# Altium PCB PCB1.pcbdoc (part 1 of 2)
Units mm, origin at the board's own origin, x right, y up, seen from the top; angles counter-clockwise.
Board outline 181.85 x 97.7 mm, 4 copper layers (Top Layer, GND, VCC, Bottom Layer); 121 components, 105 nets, 379 pads, 511 vias.
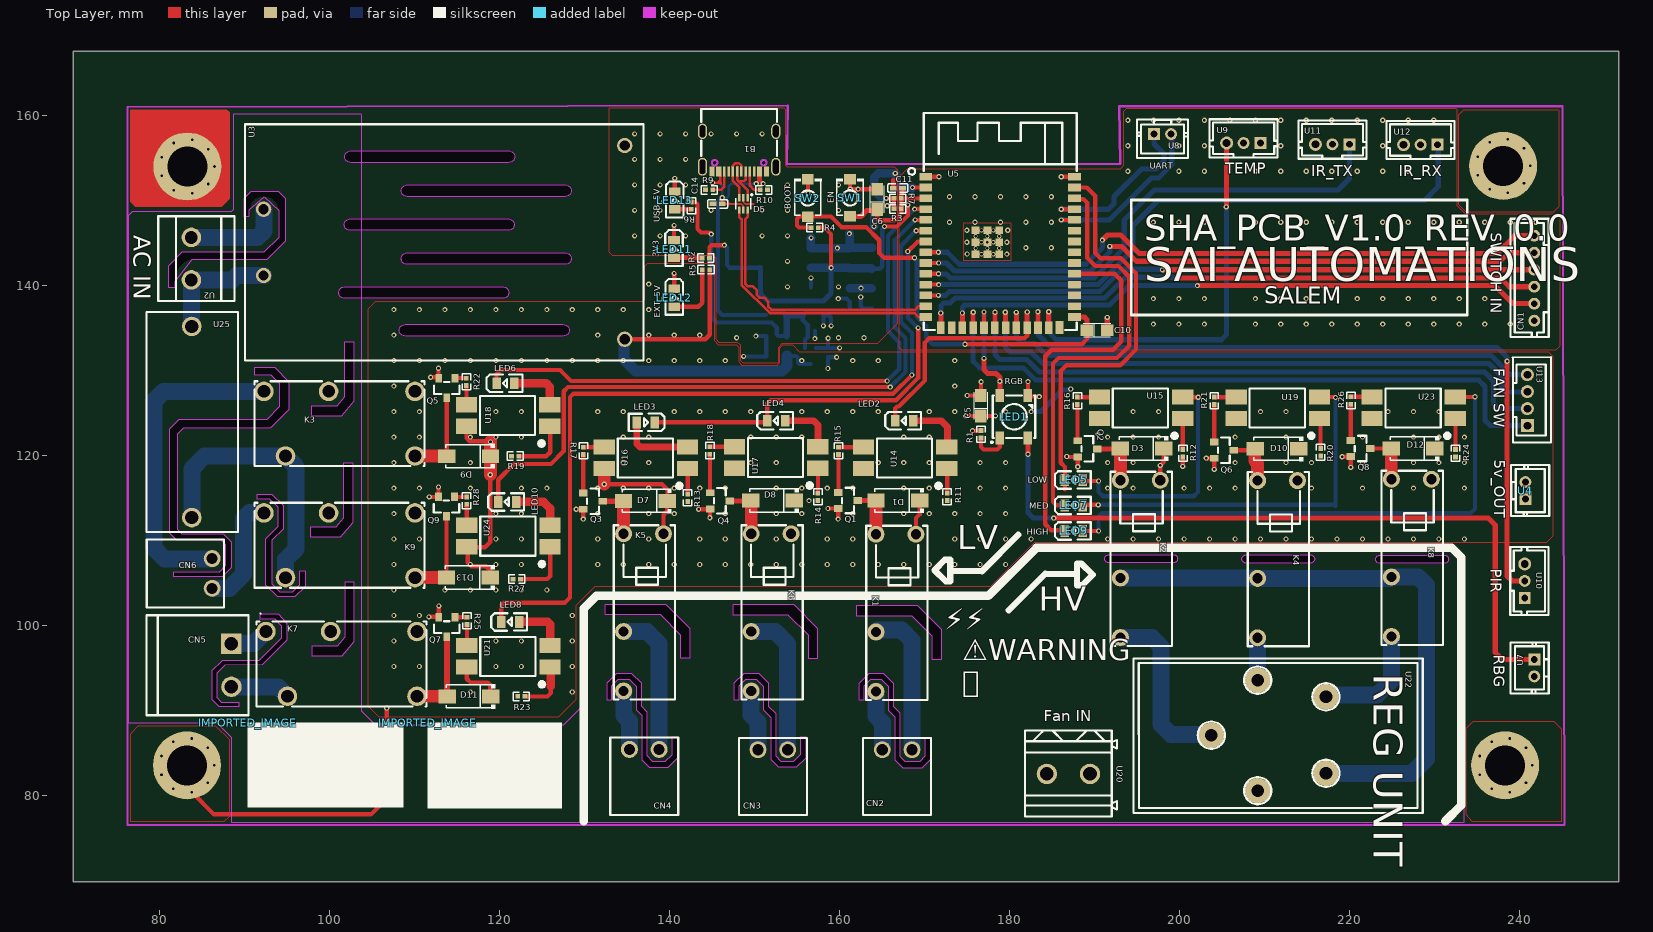
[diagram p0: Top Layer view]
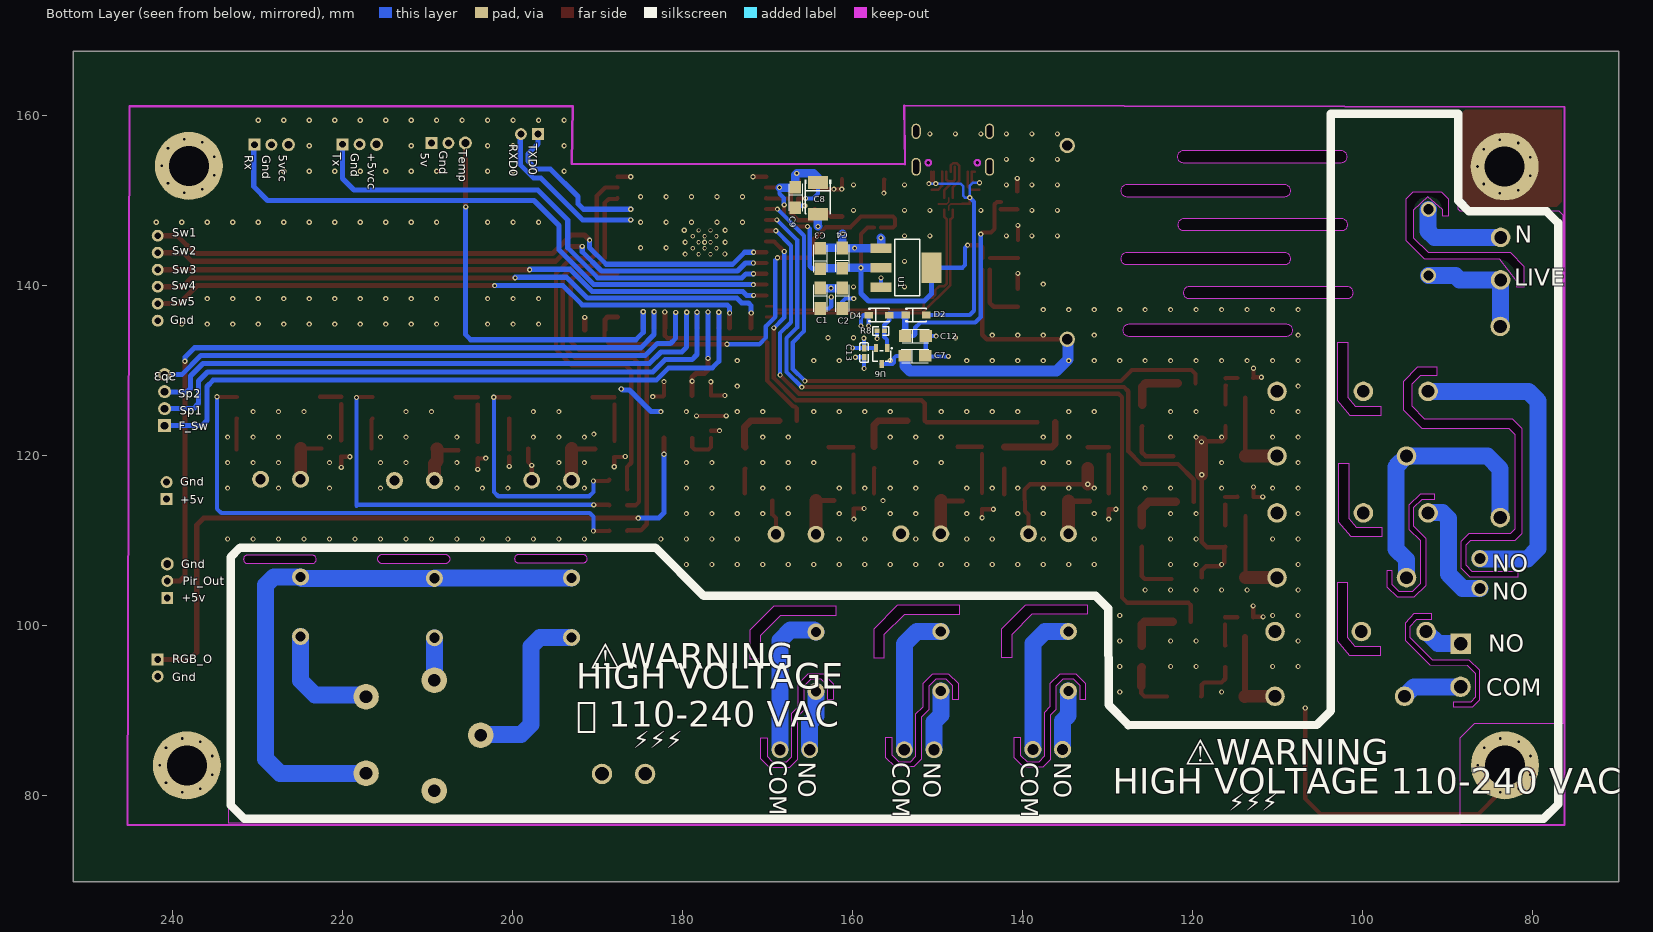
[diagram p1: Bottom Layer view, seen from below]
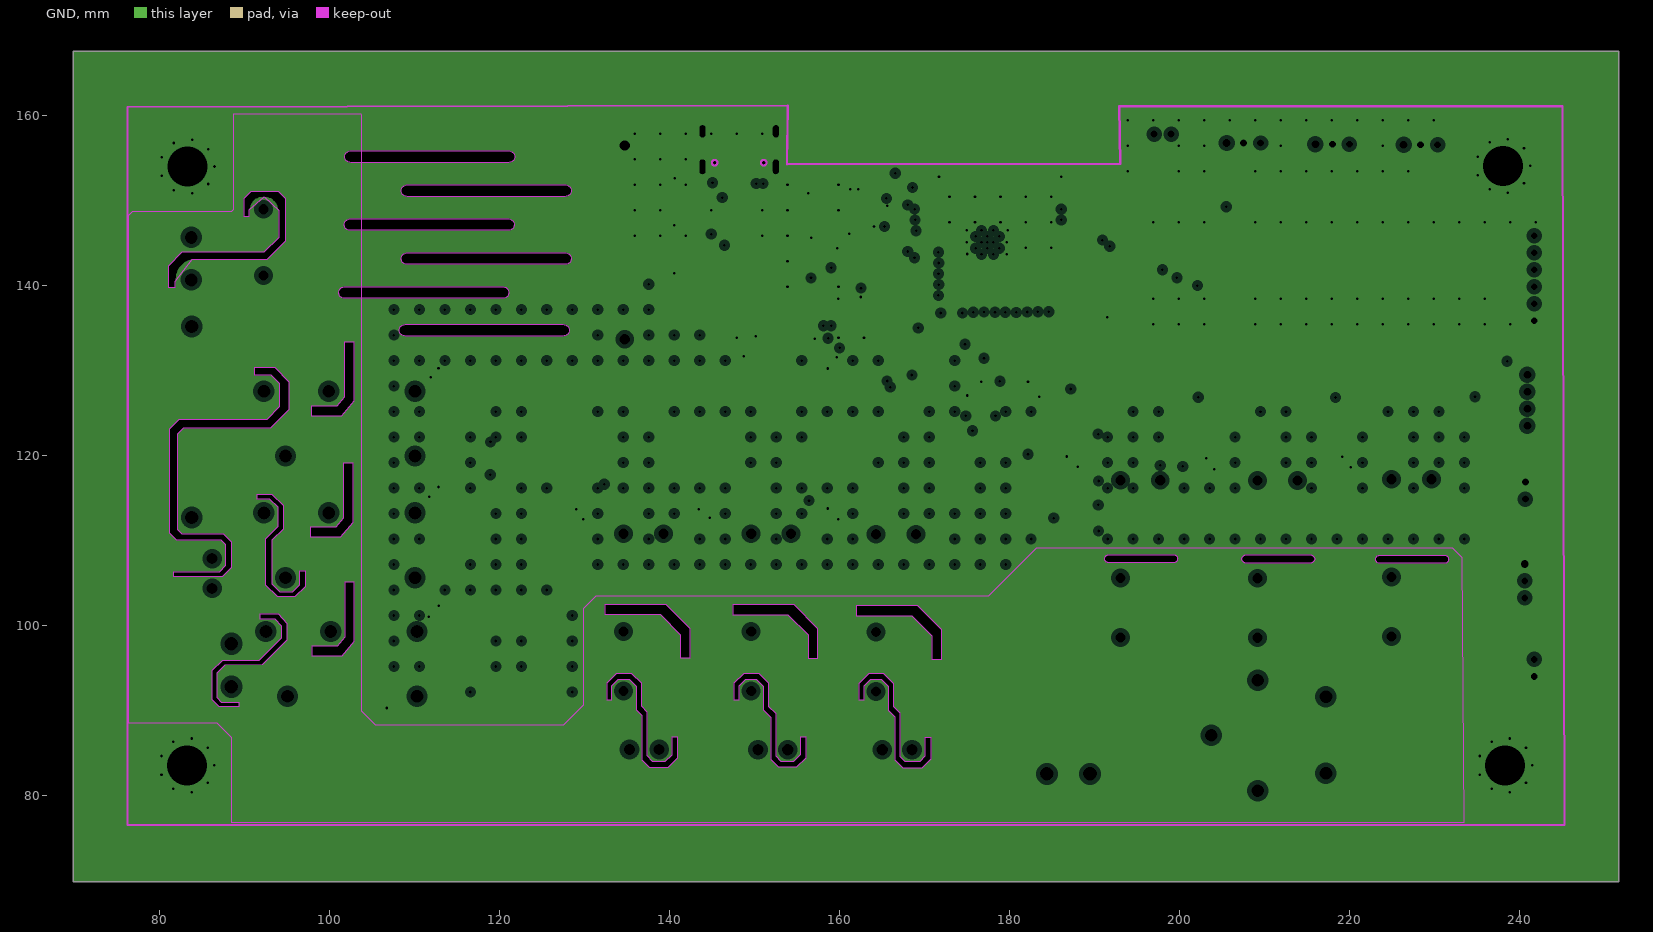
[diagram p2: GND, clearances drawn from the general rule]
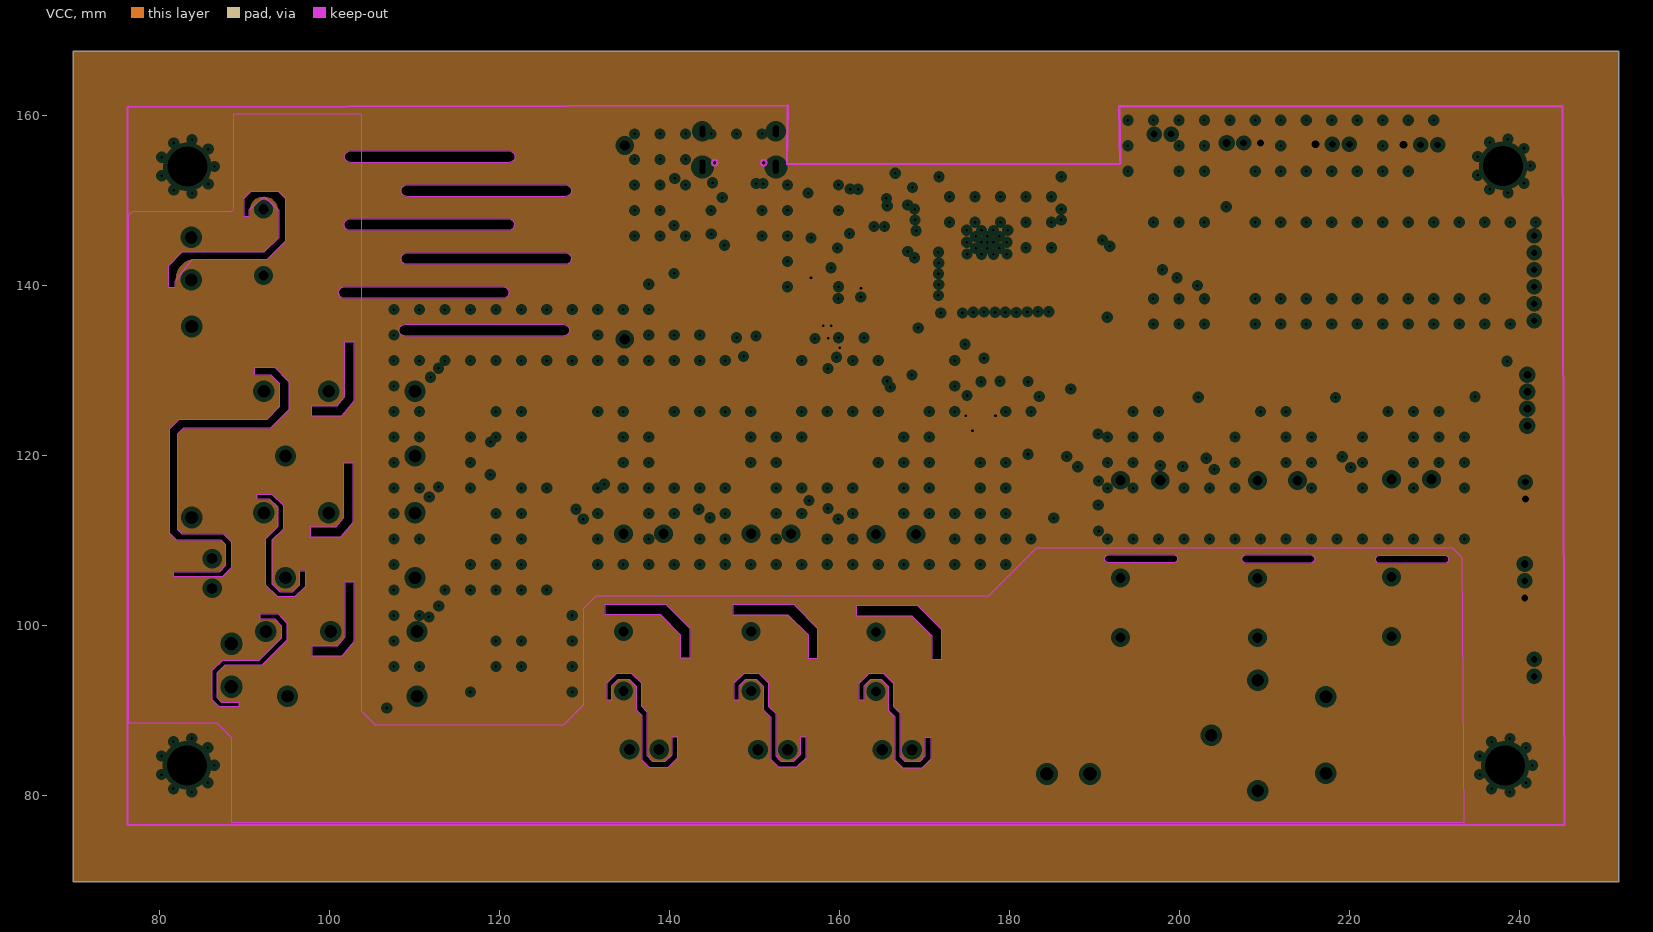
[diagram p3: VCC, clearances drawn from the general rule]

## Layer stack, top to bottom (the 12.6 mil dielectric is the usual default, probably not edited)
Top Layer: signal copper (thickness not stored)
Dielectric: dielectric 0.32, FR-4, Dk 4.8
GND: plane copper (thickness not stored)
Dielectric: dielectric 0.32, FR-4, Dk 4.8
VCC: plane copper (thickness not stored)
Dielectric: dielectric 0.32, FR-4, Dk 4.8
Bottom Layer: signal copper (thickness not stored)

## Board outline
251.698,69.85 69.85,69.85 69.85,167.555 251.698,167.555
cut-out: 102.458,155.851 121.101,155.851 cw(c121.101,155.169) 121.784,155.169 cw(c121.101,155.169) 121.101,154.486 102.458,154.486 cw(c102.458,155.169) 101.776,155.169 cw(c102.458,155.169)
cut-out: 102.4,147.851 121.043,147.851 cw(c121.043,147.169) 121.725,147.169 cw(c121.043,147.169) 121.043,146.486 102.4,146.486 cw(c102.4,147.169) 101.717,147.169 cw(c102.4,147.169)
cut-out: 101.757,139.851 120.4,139.851 cw(c120.4,139.169) 121.083,139.169 cw(c120.4,139.169) 120.4,138.486 101.757,138.486 cw(c101.757,139.169) 101.075,139.169 cw(c101.757,139.169)
cut-out: 109.108,143.851 127.751,143.851 cw(c127.751,143.169) 128.433,143.169 cw(c127.751,143.169) 127.751,142.486 109.108,142.486 cw(c109.108,143.169) 108.426,143.169 cw(c109.108,143.169)
cut-out: 109.108,151.851 127.751,151.851 cw(c127.751,151.169) 128.433,151.169 cw(c127.751,151.169) 127.751,150.486 109.108,150.486 cw(c109.108,151.169) 108.426,151.169 cw(c109.108,151.169)
cut-out: 108.874,135.43 127.517,135.43 cw(c127.517,134.747) 128.199,134.747 cw(c127.517,134.747) 127.517,134.064 108.874,134.064 cw(c108.874,134.747) 108.192,134.747 cw(c108.874,134.747)
cut-out: 191.721,108.334 199.308,108.334 cw(c199.308,107.846) 199.796,107.846 cw(c199.308,107.846) 199.308,107.358 191.721,107.358 cw(c191.721,107.846) 191.233,107.846 cw(c191.721,107.846)
cut-out: 207.86,108.303 215.447,108.303 cw(c215.447,107.815) 215.935,107.815 cw(c215.447,107.815) 215.447,107.327 207.86,107.327 cw(c207.86,107.815) 207.372,107.815 cw(c207.86,107.815)
cut-out: 223.616,108.269 231.204,108.269 cw(c231.204,107.781) 231.692,107.781 cw(c231.204,107.781) 231.204,107.293 223.616,107.293 cw(c223.616,107.781) 223.128,107.781 cw(c223.616,107.781)
cut-out: 141.249,96.182 142.418,96.182 142.418,99.636 139.598,102.456 132.359,102.456 132.359,101.292 138.882,101.292 141.249,98.925
cut-out: 156.306,96.151 157.475,96.151 157.475,99.606 154.655,102.425 147.416,102.425 147.416,101.261 153.939,101.261 156.306,98.894
cut-out: 170.891,96.042 172.06,96.042 172.06,99.497 169.24,102.316 162.001,102.316 162.001,101.152 168.524,101.152 170.891,98.785
cut-out: 97.726,111.549 97.726,110.431 101.319,110.431 102.756,112.174 102.756,119.093 101.592,119.093 101.592,112.608 100.719,111.549
cut-out: 97.841,125.811 97.841,124.693 101.434,124.693 102.87,126.436 102.87,133.355 101.706,133.355 101.706,126.871 100.833,125.811
cut-out: 97.892,97.541 97.892,96.423 101.485,96.423 102.921,98.166 102.921,105.085 101.757,105.085 101.757,98.6 100.884,97.541
cut-out: 91.164,130.365 93.529,130.365 95.193,128.701 95.193,125.399 93.005,123.211 82.795,123.211 82.078,122.494 82.078,111.294 82.608,110.765 87.494,110.765 88.392,109.866 88.392,106.775 87.331,105.714 81.694,105.714 81.656,105.752 81.656,106.349 87.046,106.349 87.788,107.091 87.788,109.484 87.237,110.035 82.02,110.035 81.182,110.873 81.182,123.149 82.316,124.284 92.631,124.284 94.144,125.797 94.144,128.432 93.15,129.426 91.164,129.426
cut-out: 91.453,115.463 93.198,115.463 94.526,114.135 94.526,111.332 93.195,110.001 93.195,104.907 94.111,103.991 95.66,103.991 96.481,104.812 96.481,106.43 97.121,106.43 97.121,104.563 95.909,103.351 93.885,103.351 92.501,104.735 92.501,110.213 93.942,111.654 93.942,113.888 92.962,114.868 91.453,114.868
cut-out: 91.858,101.387 93.921,101.373 94.936,100.275 94.936,98.242 92.044,95.35 87.65,95.3 86.739,94.389 86.739,91.528 87.255,90.969 89.288,90.969 89.288,90.407 87.012,90.407 86.205,91.28 86.205,94.701 87.436,95.932 91.727,95.932 94.358,98.562 94.358,99.921 93.604,100.738 91.858,100.738
cut-out: 133.226,91.282 133.226,92.922 133.996,93.692 135.246,93.692 136.069,92.868 136.069,90.078 136.726,89.422 136.726,84.201 137.605,83.321 139.845,83.321 140.946,84.422 140.946,86.832 140.236,86.832 140.236,84.752 139.456,83.972 138.046,83.972 137.376,84.642 137.376,89.802 136.716,90.462 136.716,93.192 135.566,94.342 133.746,94.342 132.596,93.192 132.596,91.282
cut-out: 148.211,91.277 148.211,92.917 148.981,93.687 150.231,93.687 151.054,92.863 151.054,90.073 151.921,89.207 151.921,84.236 152.8,83.357 155,83.357 156.101,84.457 156.101,86.827 155.371,86.827 155.371,84.767 154.571,83.967 153.181,83.967 152.551,84.597 152.551,89.607 151.701,90.457 151.701,93.187 150.551,94.337 148.731,94.337 147.581,93.187 147.581,91.277
cut-out: 162.905,91.242 162.905,92.882 163.675,93.652 164.925,93.652 165.749,92.828 165.749,90.038 166.505,89.282 166.505,84.221 167.455,83.272 169.775,83.272 170.795,84.292 170.795,86.792 170.065,86.792 170.065,84.622 169.425,83.982 167.735,83.982 167.155,84.562 167.155,89.662 166.395,90.422 166.395,93.152 165.245,94.302 163.425,94.302 162.275,93.152 162.275,91.242
cut-out: 81.856,139.802 81.856,140.515 cw(c84.278,140.721) 83.836,143.112 92.636,143.112 94.816,145.292 94.816,150.232 94.006,151.042 90.716,151.042 89.886,150.212 89.886,148.192 90.546,148.192 90.546,148.93 cw(c92.19,148.838) 92.286,150.482 cw(c92.234,148.702) 94.006,148.882 94.006,145.652 92.266,143.912 82.596,143.912 80.986,142.302 80.986,139.802

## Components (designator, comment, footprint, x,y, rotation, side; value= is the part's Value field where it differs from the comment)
B1 "USB_2.1" TYPE-C-SMD_SBC-160S1A-20-S412 148.202,155.79 r180 top
C1 "TAJA106K010RNJ" CASE-A_3216 163.829,138.511 r270 bottom
C2 "TAJA104K035RNJ" CASE-A_3216 161.229,138.511 r270 bottom
C3 "TAJA104K035RNJ" CASE-A_3216 163.79,143.186 r90 bottom
C4 "TAJA106K010RNJ" CASE-A_3216 161.19,143.236 r90 bottom
C5 "TAJA104K035RNJ" CASE-A_3216 176.659,125.855 r90 top
C6 "TAJA104K035RNJ" CASE-A_3216 164.452,150.153 r90 top
C7 "TAJA106K010RNJ" CASE-A_3216 152.642,131.719 r180 bottom
C8 "TAJB226K016RNJ" CASE-B_3528 164.087,150.262 r270 bottom
C9 "TAJA104K035RNJ" CASE-A_3216 166.737,150.362 r270 bottom
C10 "TAJA104K035RNJ" CASE-A_3216 190.322,134.764 r0 top
C11 "CL05A105KP5NNNC" C0402 166.878,151.478 r180 top
C12 "TAJA106K010RNJ" CASE-A_3216 152.592,134.069 r180 bottom
C13 "CL05A105KP5NNNC" C0402 158.642,132.119 r270 bottom
C14 "CL05A105KP5NNNC" C0402 145.666,149.612 r180 top
CN1 "SWITCH IN" CONN-TH_B6B-PH-K-S-GW 241.792,140.87 r270 top
CN2 "XY2500R-G-3.5-2P" CONN-TH_XY2500R-G-3.5-2P 166.791,85.371 r0 top
CN3 "XY2500R-G-3.5-2P" CONN-TH_XY2500R-G-3.5-2P 152.166,85.371 r0 top
CN4 "XY2500R-G-3.5-2P" CONN-TH_XY2500R-G-3.5-2P 137.033,85.41 r0 top
CN5 "10A" CONN-TH_2P-P5.08_XY2500R-D5.08-2P 88.437,95.316 r270 top
CN6 "10A" CONN-TH_XY2500R-G-3.5-2P 86.175,106.12 r270 top
D1 "1N4007" SMA_L4.4-W2.8-LS5.4-RD 166.869,114.7 r180 top
D2 "SD103AWS_C777800" SOD-323_L1.8-W1.3-LS2.5-FD 152.542,136.537 r0 bottom
D3 "1N4007" SMA_L4.4-W2.8-LS5.4-RD 195.614,120.823 r180 top
D4 "SD103AWS_C777800" SOD-323_L1.8-W1.3-LS2.5-FD 156.892,136.519 r0 bottom
D5 "USBLC6-2P6_C15999" SOT-666-6_L1.6-W1.2-P0.50-LS1.6-BR 148.692,149.623 r90 top
D7 "1N4007" SMA_L4.4-W2.8-LS5.4-RD 137.15,114.661 r180 top
D8 "1N4007" SMA_L4.4-W2.8-LS5.4-RD 152.127,114.7 r180 top
D9 "1N4007" SMA_L4.4-W2.8-LS5.4-RD 116.362,119.926 r180 top
D10 "1N4007" SMA_L4.4-W2.8-LS5.4-RD 211.487,120.784 r180 top
D11 "1N4007" SMA_L4.4-W2.8-LS5.4-RD 116.401,91.65 r180 top
D12 "1N4007" SMA_L4.4-W2.8-LS5.4-RD 227.517,120.823 r180 top
D13 "1N4007" SMA_L4.4-W2.8-LS5.4-RD 116.323,105.652 r180 top
IMPORTED_IMAGE "IMPORTED_IMAGE" IMPORTED_IMAGE 90.348,88.53 r0 top
IMPORTED_IMAGE "IMPORTED_IMAGE" IMPORTED_IMAGE 111.565,88.569 r0 top
K1 "ALDP105W" RELAY-TH_ALDP1XXW 166.654,101.484 r270 top
K2 "ALDP105W" RELAY-TH_ALDP1XXW 195.419,107.836 r270 top
K3 "ALQ105" RELAY-TH_ALQ1XX 101.152,123.749 r180 top
K4 "ALDP105W" RELAY-TH_ALDP1XXW 211.565,107.797 r270 top
K5 "ALDP105W" RELAY-TH_ALDP1XXW 136.945,101.538 r270 top
K6 "ALDP105W" RELAY-TH_ALDP1XXW 151.961,101.538 r270 top
K7 "ALQ105" RELAY-TH_ALQ1XX 101.386,95.472 r180 top
K8 "ALDP105W" RELAY-TH_ALDP1XXW 227.322,107.953 r270 top
K9 "ALQ105" RELAY-TH_ALQ1XX 101.152,109.435 r180 top
LED1 "RGB" LED-SMD_4P-L5.0-W5.0-BL_TC5050RGB 180.544,124.562 r90 top
LED2 "KT-0805Y" LED0805-R-RD 167.611,124.1 r0 top
LED3 "KT-0805Y" LED0805-R-RD 137.189,123.905 r180 top
LED4 "KT-0805Y" LED0805-R-RD 152.556,124.1 r0 top
LED5 "LOW" LED0805-R-RD 187.579,117.135 r0 top
LED6 "KT-0805Y" LED0805-R-RD 120.692,128.507 r0 top
LED7 "MED" LED0805-R-RD 187.579,114.135 r0 top
LED8 "KT-0805Y" LED0805-R-RD 121.238,100.426 r0 top
LED9 "HIGH" LED0805-R-RD 187.579,111.135 r0 top
LED10 "KT-0805Y" LED0805-R-RD 120.887,114.544 r0 top
LED11 "3V3" LED0805-R-RD 140.543,144.302 r270 top
LED12 "EXT_5V" LED0805-R-RD 140.557,138.565 r270 top
LED13 "USB_5V" LED0805-R-RD 140.621,150.018 r270 top
Q1 "BC547B A1G" SOT-23_L2.9-W1.3-P1.90-LS2.4-BR 161.019,114.7 r180 top
Q2 "BC547B A1G" SOT-23_L2.9-W1.3-P1.90-LS2.4-BR 189.178,120.784 r180 top
Q3 "BC547B A1G" SOT-23_L2.9-W1.3-P1.90-LS2.4-BR 130.988,114.622 r180 top
Q4 "BC547B A1G" SOT-23_L2.9-W1.3-P1.90-LS2.4-BR 145.926,114.661 r180 top
Q5 "BC547B A1G" SOT-23_L2.9-W1.3-P1.90-LS2.4-BR 113.788,127.961 r90 top
Q6 "BC547B A1G" SOT-23_L2.9-W1.3-P1.90-LS2.4-BR 205.247,120.628 r180 top
Q7 "BC547B A1G" SOT-23_L2.9-W1.3-P1.90-LS2.4-BR 113.788,99.802 r90 top
Q8 "BC547B A1G" SOT-23_L2.9-W1.3-P1.90-LS2.4-BR 221.355,120.823 r180 top
Q9 "BC547B A1G" SOT-23_L2.9-W1.3-P1.90-LS2.4-BR 113.749,113.998 r90 top
R1 "RC0402FR-073K3L" R0402 176.659,122.501 r270 top
R2 "RC0402FR-073K3L" R0402 144.272,143.248 r0 top
R3 "RC0402FR-07100KL" R0402 166.853,149.039 r0 top
R4 "RC0402FR-07100KL" R0402 157.074,146.829 r0 top
R5 "RC0402FR-073K3L" R0402 144.297,141.876 r180 top
R6 "RC0402FR-073K3L" R0402 142.566,149.412 r270 top
R7 "RC0402FR-0710KL" R0402 166.853,150.258 r180 top
R8 "RC0402FR-07100KL" R0402 156.692,134.669 r180 bottom
R9 "RC0402FR-075K1L" R0402 144.666,151.262 r0 top
R10 "RC0402FR-075K1L" R0402 151.116,151.262 r0 top
R11 "RC0402FR-071KL" R0402 172.681,115.129 r270 top
R12 "RC0402FR-071KL" R0402 200.411,120.277 r270 top
R13 "RC0402FR-071KL" R0402 142.142,115.012 r270 top
R14 "RC0402FR-071KL" R0402 157.47,115.129 r270 top
R15 "RC0402FR-071KL" R0402 159.888,120.55 r270 top
R16 "RC0402FR-071KL" R0402 188.008,126.44 r270 top
R17 "RC0402FR-071KL" R0402 129.857,120.55 r270 top
R18 "RC0402FR-071KL" R0402 144.756,120.589 r270 top
R19 "RC0402FR-071KL" R0402 121.823,119.926 r180 top
R20 "RC0402FR-071KL" R0402 216.636,120.394 r270 top
R21 "RC0402FR-071KL" R0402 204.116,126.44 r270 top
R22 "RC0402FR-071KL" R0402 116.089,128.663 r90 top
R23 "RC0402FR-071KL" R0402 122.564,91.65 r180 top
R24 "RC0402FR-071KL" R0402 232.509,120.277 r270 top
R25 "RC0402FR-071KL" R0402 116.167,100.543 r90 top
R26 "RC0402FR-071KL" R0402 220.185,126.479 r270 top
R27 "RC0402FR-071KL" R0402 122.018,105.457 r180 top
R28 "RC0402FR-071KL" R0402 116.128,114.7 r90 top
SW1 "EN" SW-SMD_L3.9-W3.0-P4.45 161.246,150.326 r90 top
SW2 "BOOT" SW-SMD_L3.9-W3.0-P4.45 156.286,150.309 r90 top
U1 "AMS1117-3.3" SOT-223-3_L6.4-W3.5-P2.30-LS7.0-BR 153.679,142.111 r0 bottom
U2 "XY126V-5.0-2P" CONN-TH_XY126V-5.0-2P 83.718,143.171 r90 top
U3 "HLK-10M05" PWRM-TH_HLK-10M05 113.476,145.082 r0 top
U4 "5v_OUT" CONN-TH_2P-P2.00_2B-PH-KL 240.739,115.87 r270 top
U5 "ESP32-S3-WROOM-1-N4R8" WIRELM-SMD_ESP32-S3-WROOM-1 178.921,143.921 r0 top
U6 "CJ3139KDW-ES" SOT-323-3_L2.1-W1.3-P1.30-LS2.3-BR 156.592,131.719 r90 bottom
U7 "RBG" CONN-TH_2P-P2.00_2B-PH-KL 241.792,95.004 r90 top
U8 "UART" CONN-TH_2P-P2.00_2B-PH-KL 198.032,157.836 r180 top
U9 "TEMP" "3 PIN JST PH" 206.573,156.783 r180 top
U10 "PIR" "3 PIN JST PH" 240.661,106.237 r90 top
U11 "IR_TX" "3 PIN JST PH" 217.026,156.627 r180 top
U12 "IR_RX" "3 PIN JST PH" 227.4,156.588 r180 top
U13 "FAN SW" "JST 4PIN" 240.973,126.518 r90 top
U14 "PC817C-MS" SOP-4_L6.5-W4.6-P2.54-LS10.0 167.728,119.731 r90 top
U15 "PC817C-MS" SOP-4_L6.5-W4.6-P2.54-LS10.0 195.497,125.621 r90 top
U16 "PC817C-MS" SOP-4_L6.5-W4.6-P2.54-LS10.0 137.228,119.731 r90 top
U17 "PC817C-MS" SOP-4_L6.5-W4.6-P2.54-LS10.0 152.556,119.77 r90 top
U18 "PC817C-MS" SOP-4_L6.5-W4.6-P2.54-LS10.0 121.004,124.724 r90 top
U19 "PC817C-MS" SOP-4_L6.5-W4.6-P2.54-LS10.0 211.604,125.621 r90 top
U20 "Fan IN" CONN-TH_2P-P5.08_DB128L-5.08-2P 186.955,82.524 r180 top
U21 "PC817C-MS" SOP-4_L6.5-W4.6-P2.54-LS10.0 121.043,96.369 r90 top
U22 "REG" "REG 1" 195.263,95.589 r270 top
U23 "PC817C-MS" SOP-4_L6.5-W4.6-P2.54-LS10.0 227.595,125.621 r90 top
U24 "PC817C-MS" SOP-4_L6.5-W4.6-P2.54-LS10.0 121.043,110.527 r90 top
U25 "0.5A 250 VAC Slow" TH_2P-BLX-A 83.772,123.944 r270 top

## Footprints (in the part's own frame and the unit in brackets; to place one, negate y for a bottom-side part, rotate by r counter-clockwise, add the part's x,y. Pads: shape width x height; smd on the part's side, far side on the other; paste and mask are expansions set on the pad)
"3 PIN JST PH" [mm]
  rect 1.4x1.4 hole 0.8: 1(-3,0)
  round 1.4 hole 0.8: 2(-1,0)
  round 1.524 hole 0.914: 3(1,0)
  silkscreen extent -5,-2.8 3,1.7
C0402 [mm]
  rect 0.79x0.54 smd: 1(-0.545,0) 2(0.545,0)
  silkscreen extent -1.17,-0.5 1.17,0.5
CASE-A_3216 [mm]
  rect 1.5x1.359 smd: 1(-1.2,0) 2(1.2,0)
  silkscreen extent -1.6,-0.8 1.6,0.8
CASE-B_3528 [mm]
  rect 1.506x2.376 smd: 1(-1.861,0) 2(1.861,0)
  silkscreen extent -2.21,-1.55 1.83,1.55
CONN-TH_2P-P2.00_2B-PH-KL [mm]
  rect 1.4x1.4 hole 0.8: 1(1,0)
  round 1.4 hole 0.8: 2(-1,0)
  silkscreen extent -3,-1.7 3,2.8
CONN-TH_2P-P5.08_DB128L-5.08-2P [mm]
  round 2.4 hole 1.6: 1(-2.54,0) 2(2.54,0)
  silkscreen extent -5.7,-5.1 5.1,5
CONN-TH_2P-P5.08_XY2500R-D5.08-2P [mm]
  rect 2.4x2.4 hole 1.6: 1(-2.54,0)
  round 2.4 hole 1.6: 2(2.54,0)
  silkscreen extent -5.88,-10 5.88,2
CONN-TH_B6B-PH-K-S-GW [mm]
  round 1.4 hole 0.8: 1(-5,0) 2(-3,0) 3(-1,0) 4(1,0) 5(3,0) 6(5,0)
  silkscreen extent -7,-2.8 6.9,1.7
CONN-TH_XY126V-5.0-2P [mm]
  round 2.3 hole 1.5: 1(-2.5,0) 2(2.5,0)
  silkscreen extent -5,-5.1 5,3.9
CONN-TH_XY2500R-G-3.5-2P [mm]
  round 2 hole 1.3: 1(-1.75,0) 2(1.75,0)
  silkscreen extent -4,-7.7 4,1.4
IMPORTED_IMAGE [mm]
  silkscreen extent 0,-9.91 18.29,0
"JST 4PIN" [mil]
  rect 60x60 hole 36: 1(-118.11,0)
  round 60 hole 36: 2(-39.37,0) 3(39.37,0) 4(118.11,0)
  silkscreen extent -197,-110 200,68
LED0805-R-RD [mm]
  rect 1x1.4 smd: 1(1.05,0) 2(-1.05,0)
  silkscreen extent -2.22,-1.04 1.99,1.01
LED-SMD_4P-L5.0-W5.0-BL_TC5050RGB [mm]
  rect 1.5x1 smd: 1(-2.5,1.65) 2(-2.5,-1.65) 3(2.5,-1.65) 4(2.5,1.65)
  silkscreen extent -3.1,-2.5 2.5,2.7
PWRM-TH_HLK-10M05 [mm]
  round 1.8 hole 1.2: 1(-21.25,3.9) 2(-21.25,-3.9) 3(21.25,11.4) 4(21.25,-11.4)
  silkscreen extent -23.45,-13.9 23.45,13.9
R0402 [mm]
  rect 0.566x0.54 smd: 1(-0.433,0) 2(0.433,0)
  silkscreen extent -0.94,-0.5 0.94,0.5
"REG 1" [mm]
  round 3 hole 1.5: 1(15.032,13.97) 2(8.509,8.509) 3(2.032,13.97) 4(3.988,21.996) P(12.988,21.996)
  silkscreen extent -0.51,-0.64 17.65,33.4
RELAY-TH_ALDP1XXW [mm]
  round 2 hole 1.2: 1(-9.25,-2.35) 2(2.25,-2.35) 3(9.25,-2.35) 4(-9.25,2.35)
  silkscreen extent -10.25,-3.5 10.25,3.71
RELAY-TH_ALQ1XX [mm]
  round 2.3 hole 1.5: 1(-8.89,-3.81) 2(1.27,-3.81) 3(8.89,-3.81) 4(6.35,3.81) 5(-8.89,3.81)
  silkscreen extent -10,-5 10,5
SMA_L4.4-W2.8-LS5.4-RD [mm]
  rect 2.046x1.62 smd: 1(-2.565,0) 2(2.565,0)
  silkscreen extent -3.08,-1.44 2.7,1.44
SOD-323_L1.8-W1.3-LS2.5-FD [mm]
  rect 1x0.8 smd: 1(-1.2,0) 2(1.2,0)
  silkscreen extent -1.2,-0.8 1.2,0.8
SOP-4_L6.5-W4.6-P2.54-LS10.0 [mm]
  rect 1.8x2.5 smd: 1(-1.27,-4.9) 2(1.27,-4.9) 3(1.27,4.9) 4(-1.27,4.9)
  silkscreen extent -3.79,-4.42 2.29,3.32
SOT-23_L2.9-W1.3-P1.90-LS2.4-BR [mm]
  rect 1x0.8 smd: 1(1.15,-0.95) 2(1.15,0.95) 3(-1.15,0)
  silkscreen extent -0.7,-1.5 0.7,1.5
SOT-223-3_L6.4-W3.5-P2.30-LS7.0-BR [mm]
  rect 2.5x1.1 smd: 1(2.97,-2.3) 2(2.97,0) 3(2.97,2.3)
  rect 2.34x3.6 smd: 4(-2.97,0)
  silkscreen extent -1.57,-3.33 1.37,3.33
SOT-323-3_L2.1-W1.3-P1.30-LS2.3-BR [mm]
  rect 0.919x0.525 smd: 1(0.95,-0.65) 2(0.95,0.65) 3(-0.95,0)
  silkscreen extent -0.62,-1.27 0.99,1.06
SOT-666-6_L1.6-W1.2-P0.50-LS1.6-BR [mm]
  rect 0.85x0.3 smd: 1(0.725,-0.5) 2(0.725,0) 3(0.725,0.5) 4(-0.725,0.5) 5(-0.725,0) 6(-0.725,-0.5)
  silkscreen extent -0.65,-1.08 1.15,0.9
SW-SMD_L3.9-W3.0-P4.45 [mm]
  rect 1.23x1.36 smd: 1(-2.185,0) 2(2.185,0)
  silkscreen extent -2.03,-1.62 2.25,1.62
TH_2P-BLX-A [mm]
  round 2.3 hole 1.55: 1(-11.25,0) 2(11.25,0)
  silkscreen extent -12.95,-5.33 12.95,5.46
TYPE-C-SMD_SBC-160S1A-20-S412 [mm]
  oval 1.1x1.8 hole 0.7 slot 1.4 at 90 deg: 1(-4.32,-2.373) 1(4.32,-2.373)
  oval 1.1x2.1 hole 0.7 slot 1.7 at 90 deg: 1(-4.32,1.807) 1(4.32,1.807)
  rect 0.3x1.15 smd: A1(-3.35,2.372) A4(-2.55,2.372) A5(-1.25,2.372) A6(-0.25,2.372) A7(0.25,2.372) A8(1.25,2.373) A9(2.55,2.372) A12(3.35,2.372) B1(3.05,2.372) B4(2.25,2.372) B5(1.75,2.372) B6(0.75,2.372) B7(-0.75,2.372) B8(-1.75,2.373) B9(-2.25,2.372) B12(-3.05,2.372)
  Multi-Layer board cut-out: 2.565,1.327 2.597,1.186 2.687,1.073 2.818,1.01 2.962,1.01 3.093,1.073 3.183,1.186 3.215,1.327 3.215,1.327 3.183,1.468 3.093,1.581 2.962,1.644 2.818,1.644 2.687,1.581 2.597,1.468 2.565,1.327
  Multi-Layer board cut-out: -3.215,1.327 -3.183,1.186 -3.093,1.073 -2.962,1.01 -2.818,1.01 -2.687,1.073 -2.597,1.186 -2.565,1.327 -2.565,1.327 -2.597,1.468 -2.687,1.581 -2.818,1.644 -2.962,1.644 -3.093,1.581 -3.183,1.468 -3.215,1.327
  silkscreen extent -4.47,-4.99 4.47,0.54
WIRELM-SMD_ESP32-S3-WROOM-1 [mm]
  rect 1.5x0.9 smd: 1(-8.75,8.895) 2(-8.75,7.625) 3(-8.75,6.355) 4(-8.75,5.085) 5(-8.75,3.815) 6(-8.75,2.545) 7(-8.75,1.275) 8(-8.75,0.005) 9(-8.75,-1.265) 10(-8.75,-2.535) 11(-8.75,-3.805) 12(-8.75,-5.075) 13(-8.75,-6.345) 14(-8.75,-7.615) 27(8.75,-7.615) 28(8.75,-6.345) 29(8.75,-5.075) 30(8.75,-3.805) 31(8.75,-2.535) 32(8.75,-1.265) 33(8.75,0.005) 34(8.75,1.275) 35(8.75,2.545) 36(8.75,3.815) 37(8.75,5.085) 38(8.75,6.355) 39(8.75,7.625) 40(8.75,8.895)
  rect 0.9x1.5 smd: 15(-6.985,-8.895) 16(-5.715,-8.895) 17(-4.445,-8.895) 18(-3.175,-8.895) 19(-1.905,-8.895) 20(-0.635,-8.895) 21(0.635,-8.895) 22(1.905,-8.895) 23(3.175,-8.895) 24(4.445,-8.895) 25(5.715,-8.895) 26(6.985,-8.865)
  rect 0.9x0.9 smd: 41(-2.9,-0.225) 41(-2.9,1.175) 41(-2.9,2.575) 41(-1.5,-0.225) 41(-1.5,1.175) 41(-1.5,2.575) 41(-0.1,-0.225) 41(-0.1,1.175) 41(-0.1,2.575)
  silkscreen extent -10.81,-9.14 9.02,16.39

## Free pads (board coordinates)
  round 8 hole 4.7: 42(83.211,83.538) 42(83.25,154.014) 42(238.125,154.092) 42(238.359,83.538)

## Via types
v1: diameter 0.61, hole 0.304, Top Layer to Bottom Layer, 331 vias
v2: diameter 0.61, hole 0.305, Top Layer to Bottom Layer, 168 vias
v3: diameter 0.5, hole 0.3, Top Layer to Bottom Layer, 12 vias

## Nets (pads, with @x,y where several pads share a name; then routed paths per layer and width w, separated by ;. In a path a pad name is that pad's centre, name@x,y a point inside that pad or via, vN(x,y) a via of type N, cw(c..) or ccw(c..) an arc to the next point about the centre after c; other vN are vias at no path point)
$1N19522: LED12.1 R5.2 | length 7.4
  Top Layer w0.5: LED12.1@140.557,137.515 140.564,137.508 143.383,137.508 143.865,137.989 R5.2@143.865,141.876
$1N20222: LED13.1 R6.2 | length 1.9
  Top Layer w0.5: LED13.1@140.621,148.967 140.633,148.979 R6.2@142.566,148.979
$1N20581: C12.1 D2.2 D4.1 R6.1 R8.2 U6.1 | length 34.3
  Top Layer w0.5: R6.1@142.566,149.845 143.009,149.845 143.281,149.573 143.281,146.677 143.697,146.262 144.716,146.262 v2(144.916,146.062)
  Bottom Layer w0.5: v2(144.916,146.062) 144.916,136.312 145.566,135.662 152.016,135.662 152.616,135.062 152.616,134.262 152.808,134.069 C12.1@153.792,134.069 ; D4.1@155.692,136.519 155.692,135.935 156.266,135.362 156.266,134.676 R8.2@156.259,134.669 156.266,134.663 156.266,133.962 155.942,133.638 U6.1@155.942,132.669
  Bottom Layer w0.8: C12.1@153.792,134.069 153.792,136.487 D2.2@153.742,136.537 155.675,136.537 D4.1@155.692,136.519
$1N21974: LED11.1 R2.1 | length 3.3
  Top Layer w0.5: LED11.1@140.543,143.252 R2.1@143.81,143.252
$1N22604: LED1.1 R1.2 | length 4.6
  Top Layer w0.5: R1.2@176.659,122.068 176.659,121.018 176.971,120.706 178.57,120.706 178.882,121.018 178.882,122.05 LED1.1@178.894,122.062
$1N26423: B1.B5 R9.2 | length 3.3
  Top Layer w0.3: R9.2@145.098,151.262 146.066,151.262 146.452,151.648 B1.B5@146.452,153.418
$1N26495: B1.A5 R10.1 | length 3.1
  Top Layer w0.3: B1.A5@149.452,153.418 149.466,153.405 149.466,151.762 149.966,151.262 R10.1@150.683,151.262
$1N98744: U2.1 U3.2 U25.1 | length 14.2
  Bottom Layer w2: U25.1@83.772,135.193 83.718,135.247 U2.1@83.718,140.671 88.55,140.671 89.061,141.182 U3.2@92.226,141.182
$2N6425: LED6.1 U18.2 | length 6.4
  Top Layer w1: LED6.1@121.742,128.507 125.489,128.507 125.918,128.078 125.918,126.008 U18.2@125.904,125.994
$2N6428: R19.1 U18.1 | length 7
  Top Layer w0.5: R19.1@122.255,119.926 125.489,119.926 125.957,120.394 125.957,123.4 U18.1@125.904,123.454
$2N6430: R22.1 U18.3 | length 2.2
  Top Layer w0.5: R22.1@116.089,128.23 116.104,128.216 U18.3@116.104,125.994
$2N7885: LED2.1 U14.2 | length 6.8
  Top Layer w0.8: LED2.1@168.661,124.1 171.979,124.1 172.72,123.359 172.72,121.094 U14.2@172.628,121.001
$2N7886: R11.1 U14.1 | length 2.9
  Top Layer w0.5: U14.1@172.628,118.461 172.681,118.408 R11.1@172.681,115.562
$2N7887: R15.1 U14.3 | length 2.9
  Top Layer w0.5: R15.1@159.888,120.983 162.81,120.983 U14.3@162.828,121.001
$2N7888: Q1.1 R15.2 | length 4.5
  Top Layer w0.5: Q1.1@159.869,115.65 159.888,115.669 R15.2@159.888,120.118
$2N18449: Q5.1 R22.2 | length 1.4
  Top Layer w0.5: Q5.1@114.738,129.111 116.074,129.111 R22.2@116.089,129.096
$2N18487: D9.2 K3.5 Q5.3 | length 10.6
  Top Layer w0.5: Q5.3@113.788,126.811 113.788,119.939 113.788,119.935 D9.2@113.797,119.926
  Top Layer w1.5: K3.5@110.042,119.939 D9.2@113.788,119.939
$2N18765: D1.2 K1.1 Q1.3 | length 6.1
  Top Layer w0.6: Q1.3@162.169,114.7 D1.2@164.304,114.7
  Top Layer w1.5: K1.1@164.304,110.735 D1.2@164.304,114.7
$2N18786: CN2.2 K1.2 | length 17.7
  Bottom Layer w2: K1.2@164.304,99.234 164.559,99.49 167.299,99.49 168.541,98.247 CN2.2@168.541,85.371
$2N22813: LED9.1 U23.2 | length 63.8
  Top Layer w0.5: LED9.1@188.63,111.135 188.652,111.112 v2(190.504,111.112) ; U23.2@232.495,126.891 234.793,126.891 v2(234.81,126.908)
  Bottom Layer w0.5: v2(190.504,111.112) 190.504,112.798 190.932,113.225 234.31,113.225 234.81,113.725 v2(234.81,126.908)
$2N22814: R24.1 U23.1 | length 3.6
  Top Layer w0.5: U23.1@232.495,124.351 232.509,124.336 R24.1@232.509,120.71
$2N22817: R26.1 U23.3 | length 2.5
  Top Layer w0.5: R26.1@220.185,126.911 222.674,126.911 U23.3@222.695,126.891
$2N22820: Q8.1 R26.2 | length 4.3
  Top Layer w0.5: R26.2@220.185,126.046 220.185,121.793 Q8.1@220.205,121.773
$2N22829: D12.2 K8.1 Q8.3 | length 6.1
  Top Layer w0.5: Q8.3@222.505,120.823 D12.2@224.952,120.823
  Top Layer w1.5: D12.2@224.952,120.823 224.952,117.223 K8.1@224.972,117.203
$2N24231: LED7.1 U19.2 | length 44.5
  Top Layer w0.5: LED7.1@188.63,114.135 188.688,114.193 v2(190.465,114.193) ; U19.2@216.504,126.891 218.33,126.891 v2(218.391,126.83)
  Bottom Layer w0.5: v2(190.465,114.193) 218.273,114.193 218.391,114.076 v2(218.391,126.83)
$2N24232: R20.1 U19.1 | length 3.6
  Top Layer w0.5: U19.1@216.504,124.351 216.636,124.219 R20.1@216.636,120.827
$2N24235: R21.1 U19.3 | length 2.6
  Top Layer w0.5: R21.1@204.116,126.872 206.686,126.872 U19.3@206.704,126.891
$2N24238: Q6.1 R21.2 | length 4.4
  Top Layer w0.5: Q6.1@204.097,121.578 204.116,121.597 R21.2@204.116,126.007
$2N24250: D10.2 K4.1 Q6.3 | length 6.4
  Top Layer w0.5: Q6.3@206.397,120.628 208.766,120.628 D10.2@208.874,120.737
  Top Layer w1.5: D10.2@208.922,120.784 208.874,120.737 208.874,119.38 209.215,119.039 K4.1@209.215,117.047
$2N24525: LED5.1 U15.2 | length 28.4
  Top Layer w0.5: LED5.1@188.63,117.135 188.763,117.001 v2(190.504,117.001) ; U15.2@200.397,126.891 200.419,126.869 v2(202.244,126.869)
  Bottom Layer w0.5: v2(190.504,117.001) 190.504,115.706 191.004,115.206 201.705,115.206 202.205,115.706 202.205,126.869 v2@202.244,126.908
$2N24526: R12.1 U15.1 | length 3.6
  Top Layer w0.5: U15.1@200.397,124.351 200.411,124.336 R12.1@200.411,120.71
$2N24529: R16.1 U15.3 | length 2.6
  Top Layer w0.5: R16.1@188.008,126.872 190.579,126.872 U15.3@190.597,126.891
$2N24532: Q2.1 R16.2 | length 4.3
  Top Layer w0.5: R16.2@188.008,126.007 188.008,121.754 Q2.1@188.028,121.734
$2N24544: D3.2 K2.1 Q2.3 | length 6.5
  Top Layer w0.6: Q2.3@190.328,120.784 193.009,120.784 D3.2@193.048,120.823
  Top Layer w1.5: D3.2@193.048,120.823 193.069,120.803 K2.1@193.069,117.086
$2N25145: LED8.1 U21.2 | length 6.3
  Top Layer w1: LED8.1@122.288,100.426 125.645,100.426 125.943,100.128 U21.2@125.943,97.639
$2N25148: R23.1 U21.1 | length 6.3
  Top Layer w0.5: R23.1@122.997,91.65 125.645,91.65 126.035,92.04 126.035,92.82
  Top Layer w1: U21.1@125.943,95.099 126.035,95.007 126.035,92.82
$2N25151: R25.1 U21.3 | length 2.5
  Top Layer w0.5: U21.3@116.143,97.639 116.167,97.664 R25.1@116.167,100.11
$2N25161: Q7.1 R25.2 | length 1.4
  Top Layer w0.5: Q7.1@114.738,100.952 114.762,100.975 R25.2@116.167,100.975
$2N25163: D11.2 K7.5 Q7.3 | length 10.6
  Top Layer w0.7: Q7.3@113.788,98.652 113.788,91.698 D11.2@113.824,91.662
  Top Layer w1.5: K7.5@110.276,91.662 113.824,91.662 D11.2@113.836,91.65
$2N25822: LED10.1 U24.2 | length 6.3
  Top Layer w1: LED10.1@121.937,114.544 125.177,114.544 125.943,113.778 U24.2@125.943,111.797
$2N25825: R27.1 U24.1 | length 7.1
  Top Layer w0.5: R27.1@122.45,105.457 125.606,105.457 125.957,105.808 125.957,109.243 U24.1@125.943,109.257
$2N25828: R28.1 U24.3 | length 2.4
  Top Layer w0.5: R28.1@116.128,114.228 116.128,111.811 U24.3@116.143,111.797
$2N25838: Q9.1 R28.2 | length 1.4
  Top Layer w0.5: Q9.1@114.699,115.148 114.714,115.133 R28.2@116.128,115.133
$2N25840: D13.2 K9.5 Q9.3 | length 10.9
  Top Layer w0.5: Q9.3@113.749,112.848 113.749,105.661 D13.2@113.758,105.652
  Top Layer w1.5: K9.5@110.042,105.625 110.069,105.652 D13.2@113.758,105.652
$2N26115: LED3.1 U16.2 | length 8.7
  Top Layer w0.8: LED3.1@136.139,123.905 136.139,121.406 136.526,121.018 139.1,121.018 139.117,121.001 U16.2@142.128,121.001
$2N26116: R13.1 U16.1 | length 3
  Top Layer w0.5: U16.1@142.128,118.461 142.142,118.447 R13.1@142.142,115.445
$2N26119: R17.1 U16.3 | length 2.5
  Top Layer w0.5: R17.1@129.857,120.983 132.31,120.983 U16.3@132.328,121.001
$2N26122: Q3.1 R17.2 | length 4.6
  Top Layer w0.5: Q3.1@129.838,115.572 129.857,115.591 R17.2@129.857,120.118
$2N26131: D7.2 K5.1 Q3.3 | length 6.3
  Top Layer w0.6: Q3.3@132.138,114.622 134.546,114.622 D7.2@134.585,114.661
  Top Layer w1.5: D7.2@134.585,114.661 134.595,114.651 K5.1@134.595,110.788
$2N47435: LED4.1 U17.2 | length 6.6
  Top Layer w0.8: LED4.1@153.606,124.1 156.963,124.1 157.47,123.593 157.47,121.055 U17.2@157.456,121.04
$2N47436: R14.1 U17.1 | length 2.9
  Top Layer w0.5: U17.1@157.456,118.5 157.47,118.486 R14.1@157.47,115.562
$2N47437: R18.1 U17.3 | length 2.9
  Top Layer w0.5: R18.1@144.756,121.022 147.638,121.022 U17.3@147.656,121.04
$2N47438: Q4.1 R18.2 | length 4.6
  Top Layer w0.5: R18.2@144.756,120.157 144.776,120.137 Q4.1@144.776,115.611
$2N47446: D8.2 K6.1 Q4.3 | length 6.4
  Top Layer w0.6: Q4.3@147.076,114.661 149.522,114.661 D8.2@149.561,114.7
  Top Layer w1.5: D8.2@149.561,114.7 149.611,114.651 K6.1@149.611,110.788
$2N52895: CN4.2 K5.2 | length 17.2
  Bottom Layer w2: K5.2@134.634,99.288 137.352,99.288 138.749,97.89 138.749,85.444 CN4.2@138.783,85.41
$2N52927: CN4.1 K5.3 | length 7.2
  Bottom Layer w2: K5.3@134.634,92.288 134.615,92.269 134.615,89.427 135.283,88.759 CN4.1@135.283,85.41
$2N65724: CN2.1 K1.3 | length 7.2
  Bottom Layer w2: K1.3@164.304,92.234 164.304,89.333 165.042,88.595 CN2.1@165.042,85.371
$2N65899: CN3.2 K6.2 | length 17.4
  Bottom Layer w2: K6.2@149.611,99.288 152.445,99.288 153.916,97.818 CN3.2@153.916,85.371
$2N65904: CN3.1 K6.3 | length 7.3
  Bottom Layer w2: K6.3@149.611,92.288 149.611,89.46 150.416,88.654 CN3.1@150.416,85.371
+3V3: C3.1 C4.1 C8.1 C9.1 R2.2 R3.1 R4.2 R7.2 U1.2 U1.4 U5.2 | length 64.3
  Top Layer w0.5: R2.2@144.705,143.248 144.705,144.528 144.713,144.528 144.947,144.762 v2(146.466,144.762) ; R4.2@157.506,146.829 158.239,146.829 159.016,146.053 v2(159.016,142.112) ; v2(165.303,146.956) 166.776,146.956 168.072,148.252 168.072,149.475 v2(168.047,149.5) ; v2(165.532,150.258) R7.2@166.42,150.258 R3.1@166.42,149.039 ; v2(168.599,151.545) U5.2@170.171,151.546
  Bottom Layer w0.5: v2(146.466,144.762) 146.766,144.462 146.766,142.412 147.066,142.111 U1.4@150.709,142.111 ; C3.1@163.79,141.986 164.753,141.986 165.049,142.283 165.049,146.702 v2(165.303,146.956) ; C8.1@164.087,152.122 164.084,152.119 164.084,150.843 164.668,150.258 v2(165.532,150.258) ; v2(168.047,149.5) 168.097,149.551 168.097,150.309 168.599,150.811 v2(168.599,151.545)
  Bottom Layer w0.6: U1.4@150.709,142.111 150.709,139.046 151.562,138.193 158.125,138.193 159.016,139.084 v2(159.016,142.112)
  Bottom Layer w1: U1.2@156.65,142.112 v2(159.016,142.112) 161.115,142.112 C4.1@161.19,142.036 163.74,142.036 C3.1@163.79,141.986 ; C8.1@164.087,152.122 164.087,152.733 164.565,153.212 v2(166.565,153.212) 166.737,153.041 166.737,151.612 166.803,151.545 v2(168.599,151.545)
+5VCC: C1.1 C2.1 C5.1 C13.1 D4.2 R1.1 U1.3 U4.1 U6.2 U9.1 U10.1 U11.3 U12.3 | length 15.4
  Top Layer w0.5: v2(174.865,124.662) 176.652,124.662 C5.1@176.659,124.655 178.358,124.655 v2(178.365,124.662) ; v2(175.666,122.928) 176.654,122.928 R1.1@176.659,122.933
  Bottom Layer w0.5: U1.3@156.649,139.811 156.659,139.821 v2(156.659,140.908) ; U6.2@157.242,132.669 158.637,132.669 C13.1@158.642,132.664 ; v2(158.116,135.262) 158.116,136.495 D4.2@158.092,136.519 158.708,136.519 159.016,136.212 v2(159.016,135.262) ; v2(158.666,133.812) 158.666,132.688 C13.1@158.642,132.664 ; v2(160.015,132.662) 160.013,132.664 C13.1@158.642,132.664
  Bottom Layer w1: C2.1@161.229,139.711 v2(162.535,139.711) C1.1@163.829,139.711
AR1: LED6.2 U5.4 | length 71.8
  Top Layer w0.5: LED6.2@119.641,128.507 119.641,129.59 120.117,130.065 127.127,130.065 128.422,128.77 v2(165.608,128.77) ; v2(168.851,149.006) U5.4@170.171,149.006
  Bottom Layer w0.5: v2(165.608,128.77) 167.035,130.197 167.035,133.312 165.71,134.637 165.71,145.864 v2(168.851,149.006)
AR2: LED8.2 U5.6 | length 94.7
  Top Layer w0.5: LED8.2@120.187,100.426 120.187,102.374 120.472,102.659 127.66,102.659 128.299,103.298 128.299,126.869 128.702,127.271 166.319,127.271 v2(168.529,129.481) ; v2(169.029,146.466) U5.6@170.171,146.466
  Bottom Layer w0.5: v2(168.529,129.481) 168.529,134.411 167.259,135.681 167.259,144.696 v2(169.029,146.466)
AR3: LED10.2 U5.5 | length 80.6
  Top Layer w0.5: LED10.2@119.836,114.544 119.836,117.148 121.705,119.016 126.06,119.016 127.559,120.515 127.559,127.559 128.059,128.059 v2(165.989,128.059) ; v2(168.902,147.736) U5.5@170.171,147.736
  Bottom Layer w0.5: v2(165.989,128.059) 167.767,129.837 167.767,133.813 166.522,135.058 166.522,145.356 v2(168.902,147.736)
AR4: LED2.2 U5.23 | length 25.9
  Top Layer w0.5: LED2.2@166.56,124.1 166.56,125.531 166.802,125.773 166.978,125.773 170.053,128.843 170.053,133.299 170.553,133.799 181.788,133.799 182.096,134.108 U5.23@182.096,135.026
  Top Layer w0.6: U5.23@182.096,135.026 v2(182.096,136.898)
AR5: LED3.2 LED4.2 U5.7 | length 52.4
  Top Layer w0.5: LED3.2@138.24,123.905 151.311,123.905 LED4.2@151.506,124.1 151.506,126.114 151.901,126.509 166.649,126.509 169.266,129.126 v2(169.266,135.018) ; v2(168.046,144.01) 169.232,145.196 U5.7@170.171,145.196
  Bottom Layer w0.5: v2(168.046,144.01) 168.046,136.238 v2(169.266,135.018)
AS1_IN: CN1.1 U5.8 | length 75.9
  Top Layer w0.5: U5.8@170.171,143.926 v2(171.653,143.926)
  Top Layer w0.6: v2(190.957,145.356) 191.557,145.956 193.126,145.956 195.301,143.781 237.388,143.781 239.477,145.87 CN1.1@241.792,145.87
  Bottom Layer w0.6: v2(171.653,143.926) 172.703,143.926 174.117,142.511 189.001,142.511 190.957,144.467 v2(190.957,145.356)
AS2_IN: CN1.2 U5.9 | length 74.7
  Top Layer w0.5: U5.9@170.171,142.656 v2(171.679,142.656)
  Top Layer w0.6: v2(191.821,144.62) 193.192,144.62 194.945,142.867 237.769,142.867 238.773,143.87 CN1.2@241.792,143.87
  Bottom Layer w0.6: v2(171.679,142.656) 172.601,142.656 173.533,141.724 189.56,141.724 191.821,143.985 v2(191.821,144.62)
AS3_IN: CN1.3 U5.12 | length 72.9
  Top Layer w0.5: U5.12@170.171,138.846 v2(171.653,138.846)
  Top Layer w0.6: v2(198.018,141.87) CN1.3@241.792,141.87
  Bottom Layer w0.5: 172.451,138.846 172.502,138.896
  Bottom Layer w0.6: v2(171.653,138.846) 172.451,138.846 ; 172.502,138.896 172.916,139.311 190.652,139.311 193.269,141.927 197.002,141.927 197.009,141.921 v2@198.018,141.921
AS4_IN: CN1.4 U5.15 | length 74.2
  Top Layer w0.6: U5.15@171.936,135.026 v2(171.936,136.771) ; v2(199.72,140.911) 237.795,140.911 238.836,139.87 CN1.4@241.792,139.87
  Bottom Layer w0.6: v2@171.936,136.847 171.936,137.638 172.263,137.965 173.054,137.965 173.613,138.524 191.211,138.524 193.675,140.987 v2@199.72,140.987
AS5_IN: CN1.5 U5.17 | length 71.7
  Top Layer w0.6: U5.17@174.476,135.026 v2(174.476,136.771) ; v2(202.133,139.997) 237.16,139.997 239.286,137.87 CN1.5@241.792,137.87
  Bottom Layer w0.6: v2@174.476,136.796 174.476,137.461 174.752,137.736 191.821,137.736 194.107,140.022 v2@202.133,140.022
COM: CN5.2 K7.4 | length 7.1
  Bottom Layer w2: CN5.2@88.437,92.776 93.922,92.776 K7.4@95.036,91.662
D+: D5.4 U5.14 | length 32.2
  Top Layer w0.3: D5.4@148.192,148.899 148.192,148.086 148.492,147.786 148.492,140.095 151.811,136.775 168.855,136.775 169.325,136.306 U5.14@170.171,136.306
D-: D5.6 U5.13 | length 32.1
  Top Layer w0.3: D5.6@149.192,148.899 149.192,148.088 148.893,147.789 148.893,140.271 149.244,139.921 149.809,139.921 150.266,139.463 150.266,138.898 150.59,138.574 151.155,138.574 151.613,138.117 151.613,137.554 151.989,137.177 168.935,137.177 169.333,137.576 U5.13@170.171,137.576
DN: B1.A7 B1.B7 D5.1 | length 6
  Top Layer w0.3: B1.A7@147.952,153.965 147.952,152.468 148.114,152.306 ; B1.B7@148.952,153.418 148.952,152.475 148.783,152.306 148.114,152.306 ; D5.1@149.192,150.348 149.192,151.229 148.114,152.306
DP: B1.A6 B1.B6 D5.3 | length 6
  Top Layer w0.3: D5.3@148.192,150.348 148.192,151.589 147.452,152.329 B1.B6@147.452,153.418 147.452,154.124 147.752,154.424 148.152,154.424 148.452,154.124 B1.A6@148.452,153.418
EN: C6.1 C11.1 R3.2 R7.1 SW1.1 U5.3 | length 13.7
  Top Layer w0.5: C6.1@164.452,148.953 164.452,147.935 164.694,147.693 166.455,147.693 167.285,148.537 R3.2@167.285,149.039 R7.1@167.285,150.258 ; 167.284,150.868 167.423,151.007 C11.1@167.423,151.478 ; 167.285,150.867 R7.1@167.285,150.258 ; U5.3@170.171,150.276 170.154,150.258 R7.1@167.285,150.258
  Top Layer w0.6: SW1.1@161.246,148.141 162.525,148.141 163.22,148.836 164.335,148.836 C6.1@164.452,148.953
